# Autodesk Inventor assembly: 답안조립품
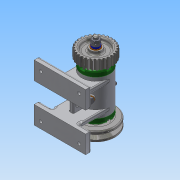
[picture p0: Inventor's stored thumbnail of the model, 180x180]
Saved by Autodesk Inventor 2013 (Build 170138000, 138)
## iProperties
Created: 2016-07
Part Number: 답안조립품
Document SubType Name: Assembly
Designer: Administrator
Author: Administrator
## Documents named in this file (16)
- C:\Users\Administrator\Desktop\460708V1025\답안조립품.iam
- C:\Users\Administrator\Desktop\460708V1025\본체.ipt
- C:\Users\Administrator\Desktop\460708V1025\V벨트풀리.ipt
- C:\Users\Administrator\Desktop\460708V1025\너트 M 8.ipt
- C:\Users\Administrator\Desktop\460708V1025\니플 M 6 x 0.75.ipt
- C:\Users\Administrator\Desktop\460708V1025\베어링 15 x 32 x 9.ipt
- C:\Users\Administrator\Desktop\460708V1025\볼트 M 6 x 8.ipt
- C:\Users\Administrator\Desktop\460708V1025\볼트 M4 x 12.ipt
- C:\Users\Administrator\Desktop\460708V1025\스퍼기어.ipt
- C:\Users\Administrator\Desktop\460708V1025\스프링와셔 8.ipt
- C:\Users\Administrator\Desktop\460708V1025\오일 실 15 25 7.ipt
- C:\Users\Administrator\Desktop\460708V1025\와셔 6x11.5.ipt
- C:\Users\Administrator\Desktop\460708V1025\와셔 8x17.ipt
- C:\Users\Administrator\Desktop\460708V1025\축.ipt
- C:\Users\Administrator\Desktop\460708V1025\커버.ipt
- C:\Users\Administrator\Desktop\460708V1025\키 3 x 3 x 12.ipt
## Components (11 placed, 3 different names)
1. V벨트풀리:1
2. KS B 2023 6002 - 15 x 32 x 9:1
3. KS B 2023 6002 - 15 x 32 x 9:2
4. ISO 4762 M4 x 12:2
5. ISO 4762 M4 x 12:3
6. ISO 4762 M4 x 12:4
7. ISO 4762 M4 x 12:5
8. ISO 4762 M4 x 12:1
9. ISO 4762 M4 x 12:6
10. ISO 4762 M4 x 12:7
11. ISO 4762 M4 x 12:8
